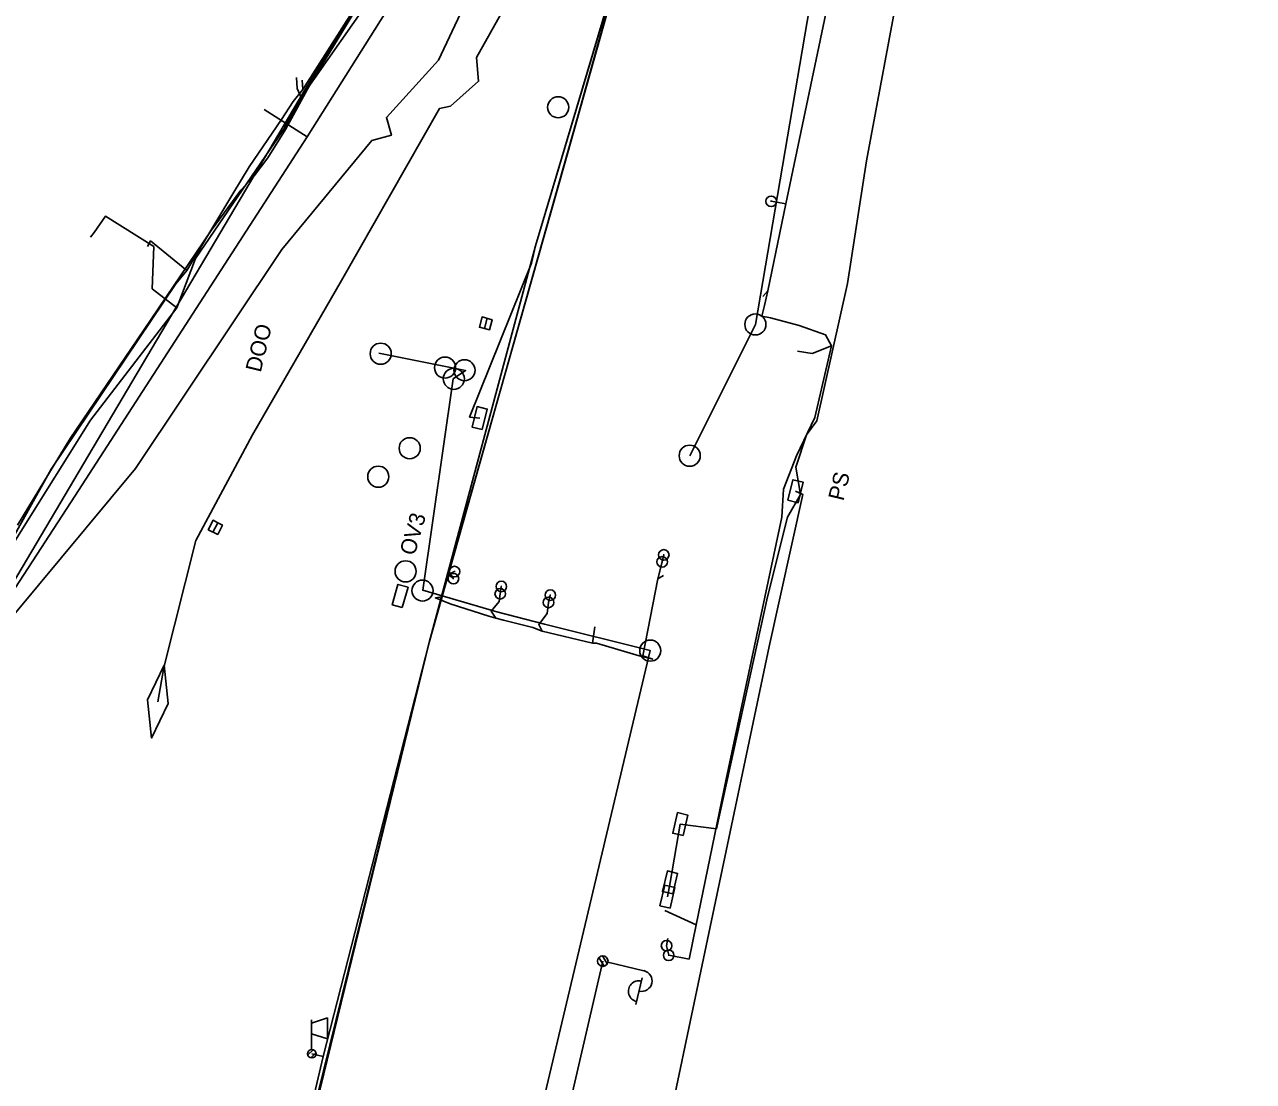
# Model space of a CAD drawing. Extents: x -748507 to -687366, y -1057342 to -1024924.
# Drawn here: x -743353.8 to -743237.3, y -1034754.6 to -1034654.5 of the extents above; entities that cross this region are included whole.
import ezdxf

# ---------------------------------------------------------------- set-up
doc = ezdxf.new("R2010")
doc.units = 0
for name, color, linetype in [('6kV - SŽDC', 7, 'Continuous'), ('DK + TKK - SŽDC', 7, 'Continuous'), ('kanalizace ČD', 7, 'Continuous'), ('PRE - NN', 7, 'Continuous'), ('PRE - OK', 7, 'Continuous'), ('PRE - VN', 7, 'Continuous'), ('Sděl MK - SŽDC', 7, 'Continuous'), ('STL - PRAŽSKÁ PLYNÁRENSKÁ', 7, 'Continuous'), ('Telefonica O2', 7, 'Continuous'), ('TK+DOK_Pha Holešovice - Kralupy', 7, 'Continuous'), ('Vedení NN - SŽDC', 7, 'Continuous')]:
    doc.layers.add(name, color=color, linetype=linetype)

msp = doc.modelspace()

# ---------------------------------------------------------------- linework, layer by layer
at = {"layer": '6kV - SŽDC'}
for points in [[(-743297.07, -1034633.77), (-743304.54, -1034646.16), (-743305.41, -1034646.57), (-743306.77, -1034650.16), (-743310.94, -1034657.62), (-743310.76, -1034659.86), (-743313.4, -1034662.22), (-743314.46, -1034662.46), (-743323.73, -1034678.74), (-743332.19, -1034693.38), (-743337.55, -1034703.39), (-743340.58, -1034715.43), (-743341.14, -1034718.66)], [(-743340.54, -1034715.21), (-743340.16, -1034718.83), (-743341.74, -1034722.11), (-743342.12, -1034718.49), (-743340.54, -1034715.21)]]:
    msp.add_lwpolyline(points, dxfattribs=at)
at = {"layer": 'DK + TKK - SŽDC'}
for p, q in [((-743283.08, -1034671.24), (-743282.98, -1034671.24)), ((-743293.26, -1034704.75), (-743293.16, -1034704.75)), ((-743313.08, -1034706.33), (-743312.98, -1034706.33)), ((-743293.41, -1034705.41), (-743293.31, -1034705.41)), ((-743313.19, -1034707), (-743313.09, -1034707)), ((-743308.75, -1034708.43), (-743308.65, -1034708.43)), ((-743308.65, -1034707.74), (-743308.55, -1034707.74)), ((-743304.01, -1034708.56), (-743303.91, -1034708.56)), ((-743304.18, -1034709.25), (-743304.08, -1034709.25)), ((-743292.99, -1034741.78), (-743292.89, -1034741.78)), ((-743292.79, -1034742.69), (-743292.69, -1034742.69))]:
    msp.add_line(p, q, dxfattribs=at)
for points in [[(-743315.44, -1034713.05), (-743314.23, -1034708.71), (-743313.63, -1034706.6), (-743302.64, -1034667.85), (-743295.6, -1034642.52)], [(-743287.3, -1034726.01), (-743282.01, -1034701.16), (-743281.85, -1034698.52), (-743280.62, -1034695.37), (-743278.88, -1034691.73), (-743277.32, -1034684.93), (-743277.88, -1034683.89), (-743280.38, -1034683), (-743283.09, -1034682.28), (-743283.91, -1034682.14), (-743283.65, -1034681.11), (-743283.36, -1034679.73), (-743281.64, -1034671.49), (-743276.03, -1034644.69)], [(-743281.64, -1034671.49), (-743283.03, -1034671.24)], [(-743283.36, -1034679.73), (-743283.81, -1034680.25)], [(-743277.32, -1034684.93), (-743279.15, -1034685.67), (-743280.55, -1034685.45)], [(-743314.23, -1034708.71), (-743314.85, -1034708.83), (-743313.46, -1034709.4), (-743309.78, -1034710.55), (-743309.12, -1034710.75), (-743308.38, -1034710.94), (-743305.6, -1034711.63), (-743304.73, -1034711.97), (-743299.96, -1034713.1), (-743299.58, -1034713.11), (-743295.54, -1034714.31), (-743294.25, -1034714.64), (-743295.2, -1034714.32), (-743293.77, -1034707.01), (-743293.36, -1034705.41), (-743293.21, -1034704.75)], [(-743313.14, -1034707), (-743313.63, -1034706.6), (-743313.03, -1034706.33)], [(-743293.77, -1034707.01), (-743293.23, -1034706.7)], [(-743309.12, -1034710.75), (-743309.57, -1034710.07), (-743308.8, -1034709.16), (-743308.7, -1034708.43), (-743308.6, -1034707.74)], [(-743304.73, -1034711.97), (-743305.03, -1034711.36), (-743304.27, -1034710.29), (-743304.13, -1034709.25), (-743303.96, -1034708.56)], [(-743299.96, -1034713.1), (-743299.75, -1034711.56)], [(-743352.85, -1034869.25), (-743345.75, -1034839.63), (-743335.08, -1034793.5), (-743334.25, -1034789.71), (-743332.49, -1034782.2), (-743315.44, -1034713.05)], [(-743290.14, -1034739.81), (-743287.3, -1034726.01)], [(-743291.38, -1034731.35), (-743292.35, -1034731.12), (-743291.9, -1034729.17), (-743290.93, -1034729.4), (-743291.38, -1034731.35)], [(-743292.86, -1034737.14), (-743292.61, -1034735.79), (-743291.64, -1034730.26), (-743288.22, -1034730.7)], [(-743292.35, -1034736.88), (-743293.33, -1034736.65), (-743292.87, -1034734.7), (-743291.9, -1034734.93), (-743292.35, -1034736.88)], [(-743292.6, -1034738.23), (-743293.58, -1034738), (-743293.12, -1034736.05), (-743292.15, -1034736.28), (-743292.6, -1034738.23)], [(-743290.14, -1034739.81), (-743293.11, -1034738.45)], [(-743292.74, -1034742.69), (-743290.81, -1034743.05), (-743290.14, -1034739.81)], [(-743292.82, -1034741.09), (-743292.94, -1034741.78), (-743292.74, -1034742.69)]]:
    msp.add_lwpolyline(points, dxfattribs=at)
for centre in [(-743283.03, -1034671.24), (-743293.36, -1034705.41), (-743293.21, -1034704.75), (-743313.03, -1034706.33), (-743313.14, -1034707), (-743308.6, -1034707.74), (-743308.7, -1034708.43), (-743304.13, -1034709.25), (-743303.96, -1034708.56), (-743292.94, -1034741.78), (-743292.74, -1034742.69)]:
    msp.add_circle(centre, 0.5, dxfattribs=at)
at = {"layer": 'kanalizace ČD'}
for points in [[(-743262.55, -1034583.82), (-743270.5, -1034614.41), (-743278.45, -1034647.33), (-743284.53, -1034682.91), (-743290.75, -1034695.35)], [(-743310.2, -1034683.29), (-743310.68, -1034683.17), (-743310.43, -1034682.2), (-743309.46, -1034682.46), (-743309.71, -1034683.42), (-743310.2, -1034683.29), (-743309.94, -1034682.33)], [(-743320.22, -1034685.64), (-743311.98, -1034687.29), (-743313.16, -1034688.05), (-743316.05, -1034708.1), (-743309.01, -1034710.14), (-743304.5, -1034711.32), (-743294.49, -1034713.82), (-743305.93, -1034762.02), (-743315.8, -1034804.22), (-743313.05, -1034808.62), (-743318.85, -1034833.3), (-743323.2, -1034836.05), (-743335.39, -1034888.56), (-743346.79, -1034941.21), (-743354.46, -1034976.19), (-743364.11, -1034973.3), (-743371.04, -1034972.55), (-743376.7, -1034992.7)], [(-743335.46, -1034701.7), (-743335.02, -1034701.92), (-743335.47, -1034702.81), (-743336.36, -1034702.36), (-743335.91, -1034701.47), (-743335.46, -1034701.7), (-743335.92, -1034702.59)]]:
    msp.add_lwpolyline(points, dxfattribs=at)
for centre in [(-743303.21, -1034662.33), (-743284.53, -1034682.91), (-743320.03, -1034685.68), (-743313.93, -1034687), (-743312.09, -1034687.25), (-743313.1, -1034688.06), (-743317.28, -1034694.64), (-743290.75, -1034695.35), (-743320.26, -1034697.34), (-743316.07, -1034708.13), (-743294.49, -1034713.82)]:
    msp.add_circle(centre, 1, dxfattribs=at)
at = {"layer": 'PRE - NN'}
msp.add_lwpolyline([(-743373.22, -1034733.88), (-743372.79, -1034733.31), (-743370.86, -1034730.74), (-743367.71, -1034726.54), (-743355.34, -1034708.17), (-743347.28, -1034694.56), (-743327.35, -1034660.91), (-743322.5, -1034653.04), (-743319.86, -1034647.3), (-743303.07, -1034615.04)], dxfattribs=at)
at = {"layer": 'PRE - OK'}
msp.add_lwpolyline([(-743322.13, -1034652.67), (-743326.9, -1034660.33), (-743329.06, -1034664.45), (-743330.72, -1034667.12), (-743332.01, -1034668.82), (-743333.28, -1034670.18), (-743336.1, -1034674), (-743342.51, -1034683.48), (-743349.44, -1034693.73), (-743354.44, -1034701.92)], dxfattribs=at)
at = {"layer": 'PRE - VN'}
msp.add_lwpolyline([(-743354.44, -1034701.92), (-743349.44, -1034693.73), (-743342.51, -1034683.48), (-743336.1, -1034674), (-743333.28, -1034670.18), (-743332.01, -1034668.82), (-743330.72, -1034667.12), (-743329.06, -1034664.45), (-743326.78, -1034660.27), (-743322.13, -1034652.67)], dxfattribs=at)
at = {"layer": 'Sděl MK - SŽDC'}
for p, q in [((-743326.58, -1034749.12), (-743325.08, -1034748.62)), ((-743326.58, -1034748.82), (-743326.57, -1034751.62)), ((-743325.08, -1034748.62), (-743325.08, -1034750.62)), ((-743325.08, -1034750.62), (-743326.58, -1034750.12)), ((-743326.93, -1034752.13), (-743326.44, -1034751.64)), ((-743326.65, -1034752.41), (-743326.16, -1034751.93))]:
    msp.add_line(p, q, dxfattribs=at)
for points in [[(-743352.91, -1034869.19), (-743345.75, -1034839.63), (-743335.08, -1034793.5), (-743334.25, -1034789.71), (-743332.49, -1034782.2), (-743325.48, -1034752.28), (-743315.44, -1034713.05), (-743314.23, -1034708.71), (-743302.64, -1034667.85), (-743295.54, -1034642.57), (-743291.41, -1034625.61), (-743289.65, -1034621.03), (-743288.28, -1034619.23), (-743271.7, -1034624.16), (-743271.33, -1034624.08), (-743270.8, -1034620.05), (-743268.89, -1034611.84)], [(-743352.85, -1034869.25), (-743345.75, -1034839.63), (-743335.08, -1034793.5), (-743334.25, -1034789.71), (-743332.49, -1034782.2), (-743315.44, -1034713.05)], [(-743325.48, -1034752.28), (-743326.55, -1034752.02)]]:
    msp.add_lwpolyline(points, dxfattribs=at)
msp.add_circle((-743326.55, -1034752.02), 0.401, dxfattribs=at)
msp.add_circle((-743326.55, -1034752.02), 0.401, dxfattribs=at)
at = {"layer": 'STL - PRAŽSKÁ PLYNÁRENSKÁ'}
msp.add_line((-743327, -1034665.14), (-743331.06, -1034662.54), dxfattribs=at)
msp.add_lwpolyline([(-743280.99, -1034562.96), (-743284.39, -1034571.91), (-743284.75, -1034573.11), (-743294.77, -1034607.06), (-743297.13, -1034613.36), (-743301.04, -1034621.39), (-743306.79, -1034632.74), (-743313.1, -1034643.06), (-743327, -1034665.14), (-743349, -1034699.17), (-743354.62, -1034707.84), (-743364.17, -1034722.22), (-743370.88, -1034733.31), (-743371.96, -1034734.74), (-743373.77, -1034737.08), (-743377.3, -1034739.58), (-743378.17, -1034740.1), (-743383.37, -1034743.1), (-743383.84, -1034743.37)], dxfattribs=at)
at = {"layer": 'Telefonica O2'}
for points in [[(-743237.34, -1034587.18), (-743246.67, -1034567.23), (-743248.26, -1034565.84), (-743251.53, -1034564.06), (-743255.45, -1034563.21), (-743258.18, -1034563.91), (-743268.61, -1034561.37), (-743270.89, -1034561.08), (-743274.61, -1034562.22), (-743276.9, -1034563.81), (-743278.44, -1034565.45), (-743279.78, -1034568.77), (-743284.99, -1034587.1), (-743290.28, -1034604.7), (-743294.12, -1034615.45), (-743298.34, -1034624.19), (-743301.04, -1034629.14), (-743314.56, -1034657.86), (-743319.49, -1034663.3), (-743319.01, -1034664.96), (-743320.86, -1034665.49), (-743329.4, -1034675.81), (-743343.26, -1034696.57), (-743359.5, -1034716.04)], [(-743327.41, -1034660.65), (-743322.5, -1034652.96), (-743314.35, -1034638.88), (-743310.68, -1034626.6), (-743304.99, -1034607.94), (-743300.92, -1034588.88), (-743295.34, -1034569.86)], [(-743314.55, -1034642.44), (-743320.2, -1034650.89), (-743327.55, -1034661.4)], [(-743327.55, -1034661.4), (-743327.95, -1034660.54), (-743328.01, -1034659.52)], [(-743327.41, -1034660.65), (-743327.46, -1034659.75)], [(-743329.42, -1034663.48), (-743328.31, -1034661.77), (-743327.41, -1034660.65)], [(-743339.35, -1034681.33), (-743337.58, -1034676.67), (-743329.2, -1034664.4), (-743327.55, -1034661.4)], [(-743327.55, -1034661.4), (-743329.2, -1034664.4)], [(-743332.48, -1034667.96), (-743329.42, -1034663.48)], [(-743332.48, -1034667.96), (-743334.04, -1034670.53)], [(-743334.04, -1034670.53), (-743338.41, -1034677.8)], [(-743339.35, -1034681.33), (-743341.69, -1034679.52), (-743341.52, -1034675.53), (-743346.11, -1034672.66), (-743347.19, -1034674.21), (-743347.51, -1034674.64)], [(-743338.41, -1034677.8), (-743341.83, -1034675), (-743342.12, -1034675.51)], [(-743339.43, -1034679.07), (-743338.41, -1034677.8)], [(-743382.35, -1034730.86), (-743376.67, -1034733.58), (-743374.46, -1034734.64), (-743373.76, -1034734.78), (-743367.57, -1034725.7), (-743363.27, -1034718.2), (-743351.25, -1034696.62), (-743339.43, -1034679.07)], [(-743339.35, -1034681.33), (-743347.51, -1034691.97), (-743354.13, -1034702.52), (-743357.09, -1034707.29), (-743360.04, -1034712.8), (-743360.65, -1034715.38), (-743361.29, -1034716.36), (-743362.74, -1034718.6), (-743363.01, -1034719.01)]]:
    msp.add_lwpolyline(points, dxfattribs=at)
at = {"layer": 'TK+DOK_Pha Holešovice - Kralupy'}
for points in [[(-743348.28, -1034838.87), (-743345.94, -1034839.57), (-743334.25, -1034789.71), (-743332.49, -1034782.2), (-743315.44, -1034713.05), (-743314.23, -1034708.71), (-743313.63, -1034706.6), (-743302.64, -1034667.85), (-743295.6, -1034642.52), (-743289.66, -1034619.88), (-743287.21, -1034611.85), (-743285.25, -1034610.91)], [(-743345.94, -1034839.57), (-743335.08, -1034793.5), (-743334.25, -1034789.71), (-743332.49, -1034782.2), (-743315.44, -1034713.05), (-743314.23, -1034708.71), (-743313.63, -1034706.6), (-743302.64, -1034667.85), (-743295.6, -1034642.52)]]:
    msp.add_lwpolyline(points, dxfattribs=at)
at = {"layer": 'Vedení NN - SŽDC'}
for p, q in [((-743299.36, -1034742.91), (-743298.86, -1034743.72)), ((-743299.02, -1034742.74), (-743298.56, -1034743.49)), ((-743298.5, -1034743.35), (-743295.1, -1034744.15)), ((-743295.26, -1034744.83), (-743295.85, -1034747.36))]:
    msp.add_line(p, q, dxfattribs=at)
for points in [[(-743305.35, -1034675.45), (-743295.55, -1034642.56), (-743286.8, -1034611.71), (-743285.13, -1034610.19), (-743283.47, -1034603.9), (-743285.15, -1034603.57), (-743285.32, -1034604.23), (-743284.52, -1034604.77)], [(-743352.92, -1034869.25), (-743345.75, -1034839.63), (-743335.08, -1034793.5), (-743315.44, -1034713.05), (-743305.35, -1034675.45), (-743295.56, -1034642.57), (-743295.29, -1034641.55), (-743291.69, -1034628.1), (-743286.74, -1034609.65), (-743286.05, -1034607.39)], [(-743288.28, -1034619.23), (-743282.74, -1034622.16), (-743271.7, -1034624.16), (-743271.78, -1034626.51), (-743270.19, -1034627.66), (-743266.38, -1034628.5), (-743269.56, -1034641.1), (-743270.7, -1034646.06), (-743271.01, -1034651.3), (-743273.99, -1034667.4), (-743275.8, -1034679.02), (-743278.71, -1034692.05), (-743279.7, -1034693.38), (-743280.68, -1034696.43), (-743280.25, -1034699.02), (-743281.48, -1034701.17), (-743283.39, -1034708.73), (-743288.22, -1034730.7)], [(-743335.08, -1034793.5), (-743315.44, -1034713.05), (-743295.54, -1034642.57)], [(-743310.65, -1034691.78), (-743311.6, -1034691.69), (-743305.75, -1034677.11), (-743305.35, -1034675.45)], [(-743310.4, -1034692.87), (-743311.37, -1034692.63), (-743310.9, -1034690.69), (-743309.93, -1034690.93), (-743310.4, -1034692.87)], [(-743280.47, -1034699.8), (-743281.44, -1034699.56), (-743280.97, -1034697.62), (-743280, -1034697.86), (-743280.47, -1034699.8)], [(-743343.96, -1034960.72), (-743342.1, -1034960.98), (-743338.7, -1034946.96), (-743338.03, -1034943.87), (-743330.82, -1034914.46), (-743322.71, -1034880.96), (-743320.24, -1034874.81), (-743306.37, -1034809.66), (-743302.28, -1034793.57), (-743299.61, -1034791.32), (-743283.23, -1034713.42), (-743280.02, -1034699.03), (-743280.72, -1034698.71)], [(-743317.98, -1034709.74), (-743318.94, -1034709.47), (-743318.4, -1034707.54), (-743317.44, -1034707.81), (-743317.98, -1034709.74)], [(-743331.38, -1034874.24), (-743328.48, -1034862.09), (-743327.15, -1034856.26), (-743326.42, -1034856.15), (-743309.43, -1034785.67), (-743308.43, -1034785), (-743306.71, -1034777.52), (-743302.84, -1034759.89), (-743298.99, -1034743.24)]]:
    msp.add_lwpolyline(points, dxfattribs=at)
for centre, radius in [((-743317.67, -1034706.31), 1), ((-743298.99, -1034743.24), 0.5), ((-743298.99, -1034743.24), 0.5)]:
    msp.add_circle(centre, radius, dxfattribs=at)
for centre, start, end in [((-743295.32, -1034745.12), 256.8377, 76.8377), ((-743295.56, -1034746.1), 76.1351, 257.5402)]:
    msp.add_arc(centre, 1, start, end, dxfattribs=at)

# ---------------------------------------------------------------- texts
for s, rotation, p in [('DOO', 76.369, (-743331.4, -1034687.52)), ('PS', 76.3653, (-743276.19, -1034699.7)), ('OV3', 74.1264, (-743316.82, -1034704.89))]:
    msp.add_text(s, height=1.5, rotation=rotation, dxfattribs=at).set_placement(p)

doc.saveas('drawing.dxf')
